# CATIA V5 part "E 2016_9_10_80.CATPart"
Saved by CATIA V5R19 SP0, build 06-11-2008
Nomenclature: E 2016_9_10_80
Description: PART-E 2016_9_10_80-DESC
Property "Material": "2.0401 (CuZn)"
Property "Hersteller": "Meusburger"
Property "Bestellnummer": "E2016/9/10/80"
Property "Teilenummer": "E2016/9/10/80"
Property "Beschreibung": "Anschlussnippel mit Verlängerung und Gewinde _ Fitting with extension, threaded"
Material "Brass": density 8216 kg/m3, Young's modulus 1.31e+11 Pa, Poisson ratio 0.35, thermal expansion 1.67e-05 1/K
Bounding box of the stored display mesh (mm): x -6.351 to 6.351, y -5.5 to 5.5, z -59 to 21
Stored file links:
  G:\UTB\Kombinované\Bakalářská práce\Catia\FORMA\E 2016_9_10_80.CATPart
  D:\Aplikace\CATIA\Nová složka\win_b64\startup\materials\Catalog.CATMaterial
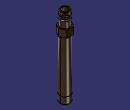
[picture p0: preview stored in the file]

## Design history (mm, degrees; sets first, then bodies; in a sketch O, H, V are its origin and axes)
Body1 "E 2016_9_10_80" (main body)
  Solid1: solid without history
